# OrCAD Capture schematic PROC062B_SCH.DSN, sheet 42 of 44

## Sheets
42 42. PERIPHERAL POWER SUPPLY: size C; title: PERIPHERAL POWER SUPPLY
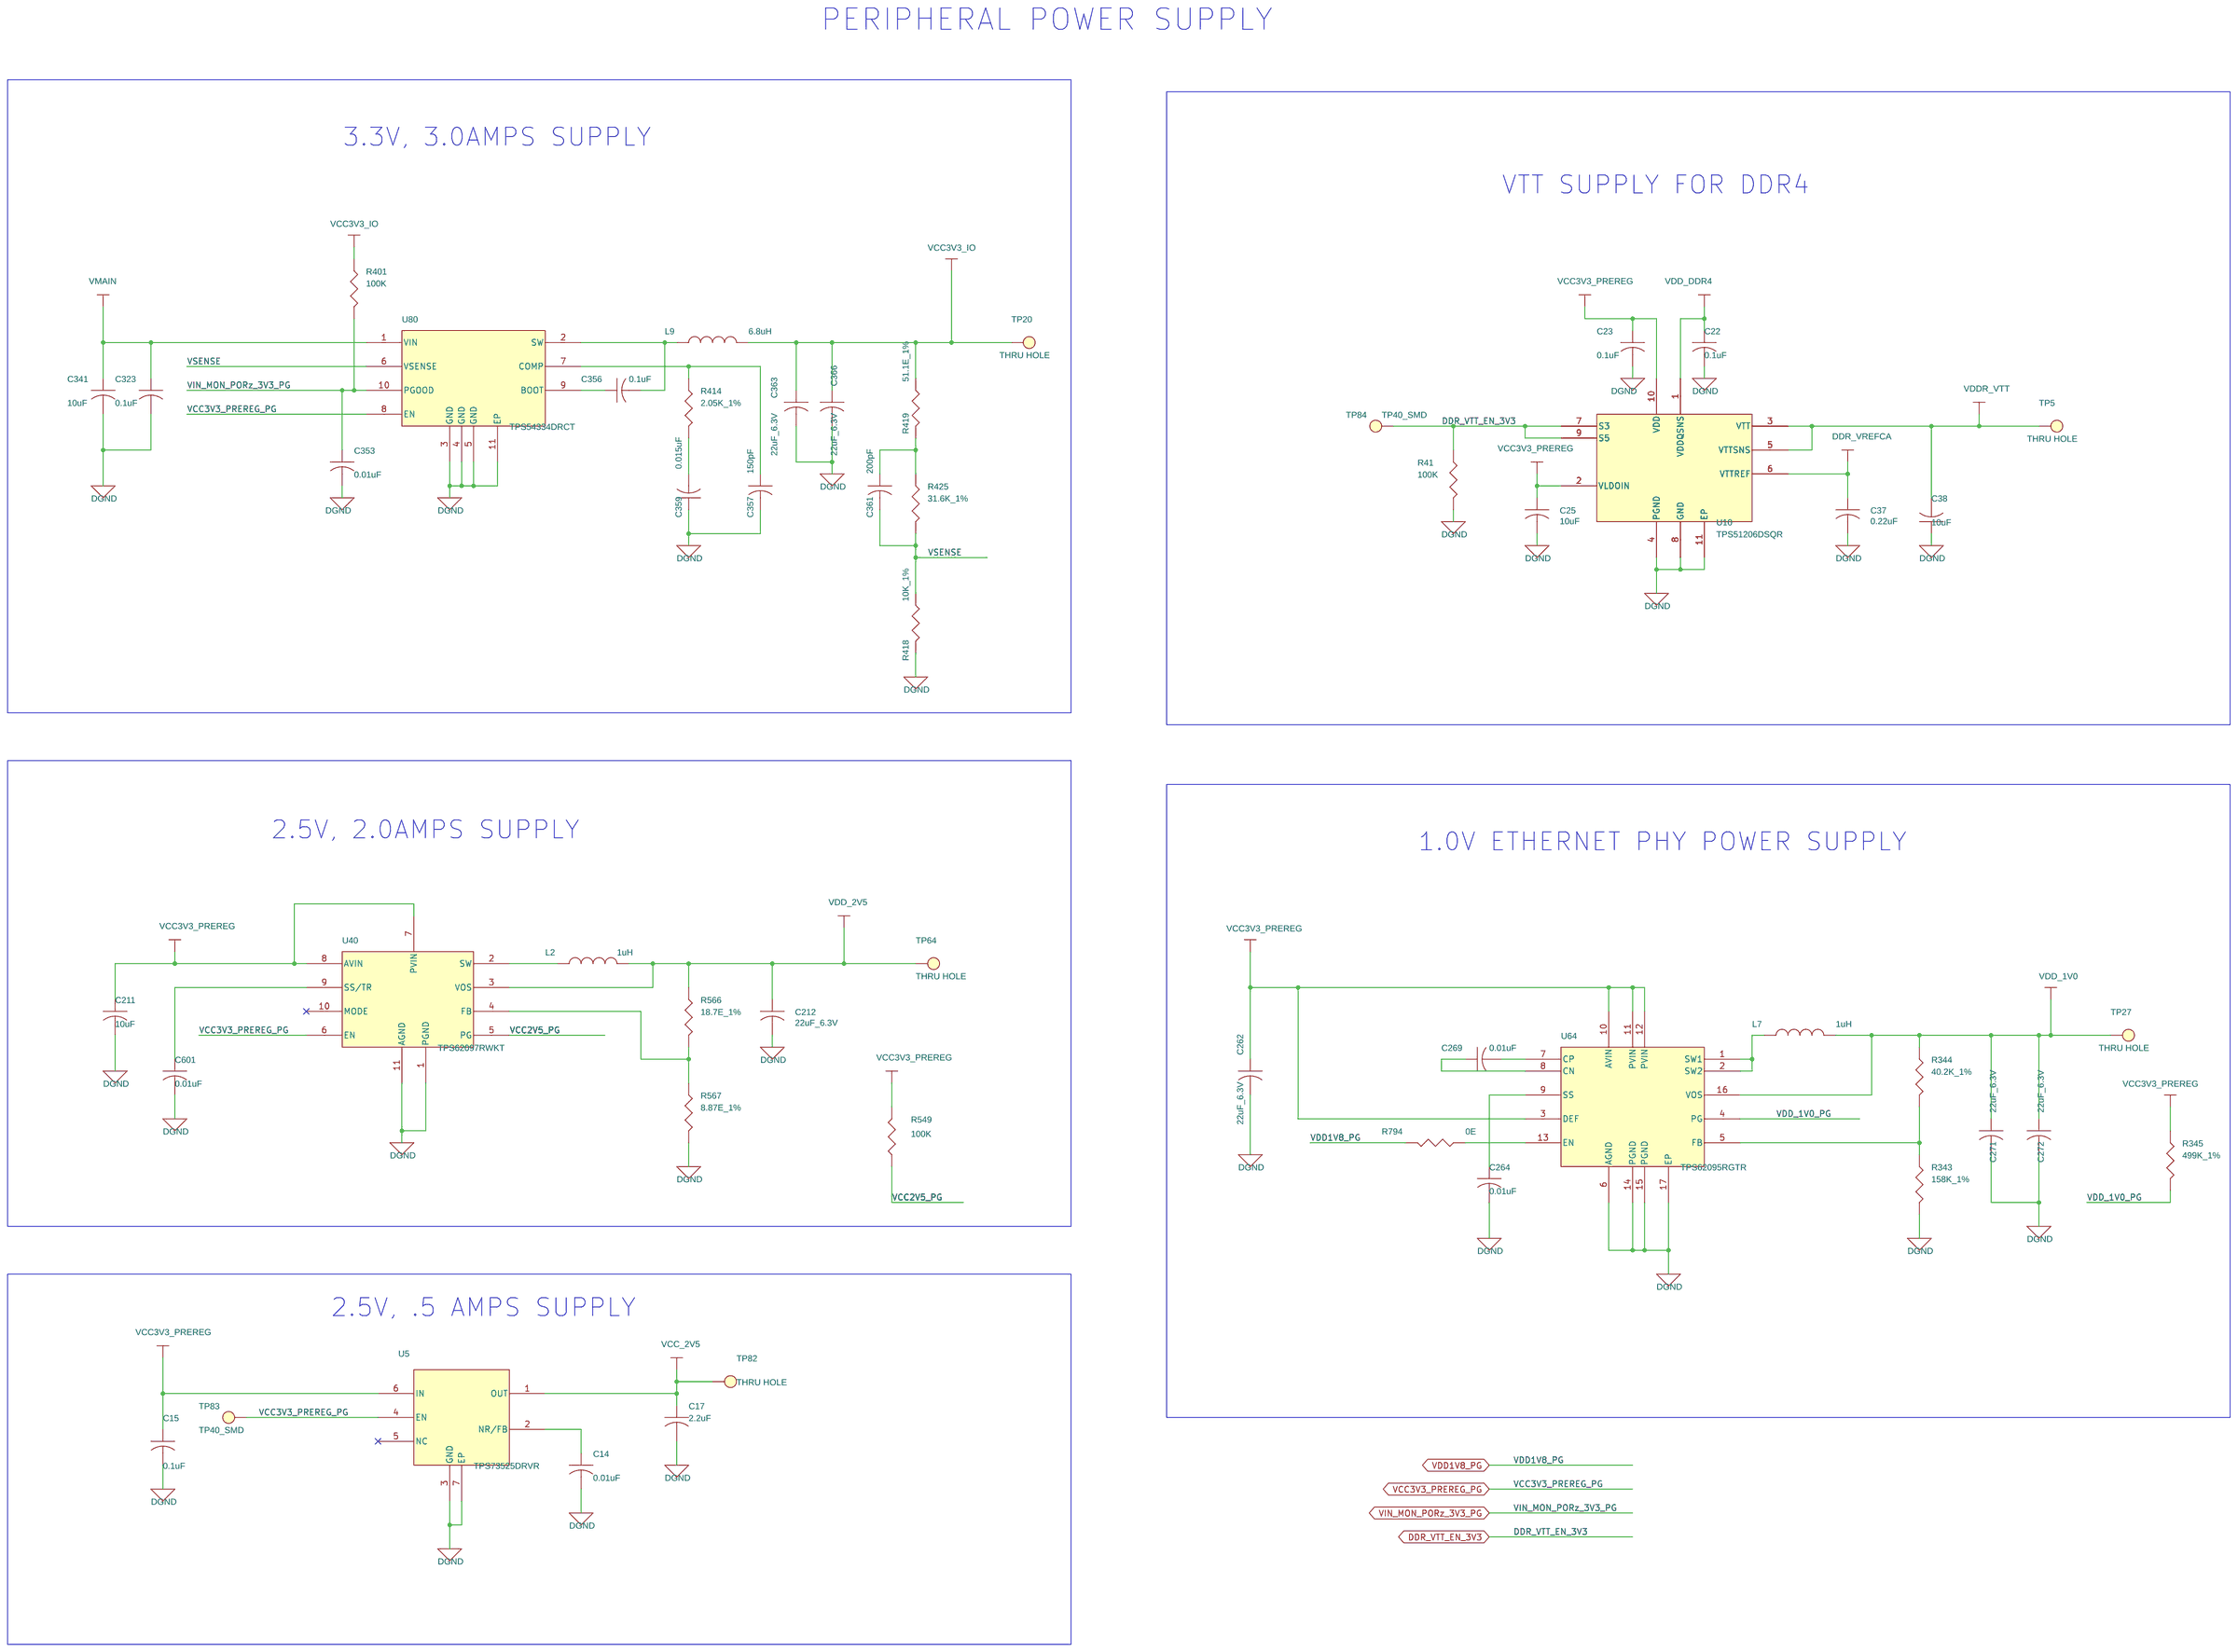
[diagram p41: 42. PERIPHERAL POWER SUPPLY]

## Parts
C14  0.01uF  [CAP0201_0-5]
C15  0.1uF  [CAP0201_0-5]
C17  2.2uF  [CAP0402_0-75]
C22  0.1uF  [CAP0201_0-5]
C23  0.1uF  [CAP0201_0-5]
C25  10uF  [CAP0603_1]
C37  0.22uF  [CAP0402_0-75]
C38  10uF  [CAP0603_1]
C211  10uF  [CAP0603_1]
C212  22uF_6.3V  [CAP0603]
C262  22uF_6.3V  [CAP0603]
C264  0.01uF  [CAP0201_0-5]
C269  0.01uF  [CAP0201_0-5]
C271  22uF_6.3V  [CAP0603]
C272  22uF_6.3V  [CAP0603]
C323  0.1uF  [CAP0603_1]
C341  10uF  [CAP1206_2]
C353  0.01uF  [CAP0201_0-5]
C356  0.1uF  [CAP0201_0-5]
C357  150pF  [CAP0402_0-75]
C359  0.015uF  [CAP0402_0-75]
C361  200pF  [CAP0402_0-75]
C363  22uF_6.3V  [CAP0603]
C366  22uF_6.3V  [CAP0603]
C601  0.01uF  [CAP0201_0-5]
L2  1uH  [IND_IHLP2020AB_210X210_SMD_1-2]
L7  1uH  [IND_XFL4020_170X170_SMD_2-1]
L9  6.8uH  [IND_74439346068_260X270_SMD_6-1]
R41  100K  [RES0402_0-5]
R343  158K_1%  [RES0402_0-5]
R344  40.2K_1%  [RES0402_0-5]
R345  499K_1%  [RES0402]
R401  100K  [RES0402_0-5]
R414  2.05K_1%  [RES0402]
R418  10K_1%  [RES0402_0-5]
R419  51.1E_1%  [RES0402_0-5]
R425  31.6K_1%  [RES0402]
R549  100K  [RES0402_0-5]
R566  18.7E_1%  [RES0402]
R567  8.87E_1%  [RES0402]
R794  0E  [RES0402_0-5]
TP5  THRU HOLE  [TP_40X65]
TP20  THRU HOLE  [TP_40X65]
TP27  THRU HOLE  [TP_40X65]
TP64  THRU HOLE  [TP_40X65]
TP82  THRU HOLE  [TP_40X65]
TP83  TP40_SMD  [TP40_SMD]
TP84  TP40_SMD  [TP40_SMD]
U5  TPS73525DRVR  [SON6_25-59_85X85_0-8]
U10  TPS51206DSQR  [DFN10_15-74_80X80_0-8]
U40  TPS62097RWKT  [VQFNHR11_TPS62097_80X80_1]
U64  TPS62095RGTR  [QFN16_19-68_120X120_1]
U80  TPS54334DRCT  [SON10_19-68_125X125_1]

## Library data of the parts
C14 C264 C269 C353 C601 = CAP: CAP CERAMIC 0.01uF 25V 10% X5R 0201; Chkd/date: MANIRAJA/230118; Crtd /date: MANIRAJA/230118; Custom_Duty: 15%; Customs_HS_Code: 85322990; Distributor_name: DIGIKEY; Distributor_part_number: GRM033R61E103KA12J-ND; Height: 0.33MM; Mfr_name: MURATA; Mfr_part_number: GRM033R61E103KA12J; Mistral Part No: 120018010007-R; Package: 0201; Part_type: CAPACITORS\CERAMIC; Project: TI_MAXIE_CPB; RoHS: RoHS; Temperature: -55°C+85°C; Tolerance: 10%; Voltage: 25V; Wattage: NA; Weight: 0.33mg; Datasheet: Y:\MIS_DATABASE\DATASHEETS\CAPACITORS\GRM033R61E103KA12.PDF
C15 C22 C23 C356 = CAP: CAP CERAMIC 0.1uF 16V 10% X5R 0201; Chkd/date: MANIRAJA/120218; Crtd /date: MANIRAJA/120218; Custom_Duty: 15%; Customs_HS_Code: 85322990; Distributor_name: DIGIKEY; Distributor_part_number: 490-16742-1-ND; Height: 0.33MM; Mfr_name: MURATA; Mfr_part_number: GRM033R61C104KE84J; Mistral Part No: 120009030072-R; Package: 0201; Part_type: CAPACITORS\CERAMIC; Project: TI_MAXIE_CPB; RoHS: RoHS; Temperature: -55°C+85°C; Tolerance: 10%; Voltage: 16V; Wattage: NA; Weight: 0.33mg; Datasheet: Y:\MIS_DATABASE\DATASHEETS\CAPACITORS\GRM033R61C104KE84.PDF
C17 = CAP: CAP CERAMIC 2.2uF 10V 20% X5R 0402; Chkd/date: MANIRAJA/240118; Crtd /date: MANIRAJA/240118; Custom_Duty: 15%; Customs_HS_Code: 85322990; Distributor_name: DIGIKEY; Distributor_part_number: 490-12254-1-ND; Height: 0.55MM; Mfr_name: MURATA; Mfr_part_number: GRT155R61A225ME01D; Mistral Part No: 120018010016-R; Package: 0402; Part_type: CAPACITORS\CERAMIC; Project: TI_MAXIE_CPB; RoHS: RoHS; Temperature: -55°C+85°C; Tolerance: 20%; Voltage: 10V; Wattage: NA; Weight: 0.65mg; Datasheet: Y:\MIS_DATABASE\DATASHEETS\CAPACITORS\GRT155R61A225ME01.PDF
C25 C38 C211 = CAP: CAP CERAMIC 10uF 10V 10% X5R 0603; Chkd/date: MANIRAJA/230118; Crtd /date: MANIRAJA/230118; Custom_Duty: 15%; Customs_HS_Code: 85322990; Distributor_name: DIGIKEY; Distributor_part_number: 478-10766-1-ND; Height: 0.94MM; Mfr_name: AVX CORPORATION; Mfr_part_number: 0603ZD106KAT2A; Mistral Part No: 120010080001-R; Package: 0603; Part_type: CAPACITORS\CERAMIC; Project: TI_MAXIE_CPB; RoHS: RoHS; Temperature: -55°C+85°C; Tolerance: 10%; Voltage: 10V; Wattage: NA; Weight: 2mg; Datasheet: Y:\MIS_DATABASE\DATASHEETS\CAPACITORS\AVX_MLC.PDF
C37 = CAP: CAP CERAMIC 0.22uF 10V 10% X5R 0402; Chkd/date: MANIRAJA/070220; Crtd /date: ALVY/070220; Custom_Duty: 15%; Customs_HS_Code: 85322990; Distributor_name: DIGIKEY; Distributor_part_number: 587-1228-1-ND; Footprint Path: Y:\MIS_DATABASE\Library\ALTIUM_TOOL\PCB_FOOTPRINTS\Altium_Footprint_Lib.PcbLib; Height: 0.55MM; Library Path: Y:\MIS_DATABASE\Library\ALTIUM_TOOL\SCHEMATICS_PARTS\MS_DISCRETE_Library.schlib; Mfr_name: TAIYO YUDEN; Mfr_part_number: LMK105BJ224KV-F; Mistral Part No: 120009030090-R; Package: 0402; Part_type: CAPACITORS\CERAMIC; Project: TI_MAXIE_CPB; RoHS: RoHS; Temperature: -55°C+85°C; Tolerance: 10%; Voltage: 10V; Wattage: NA; Weight: 0.65mg; Datasheet: Y:\MIS_DATABASE\DATASHEETS\CAPACITORS\LMK105BJ224KV-F.PDF
C212 C262 C271 C272 C363 C366 = CAP: CAP CERAMIC 22uF 6.3V 20% X5R 0603; Alternate_mfr_name_A: YAGEO AMERICA; Alternate_mfr_part_number_A: CC0603MRX5R5BB226; Chkd/date: JEBRAN/090915; Crtd /date: JEBRAN/090915; Custom_Duty: 15%; Customs_HS_Code: 85322990; Distributor_name: DIGIKEY; Distributor_name_A: DIGIKEY; Distributor_part_number: 490-7611-2-ND; Distributor_part_number_A: 311-1815-1-ND; Height: 1.00MM; Mfr_name: MURATA; Mfr_part_number: GRM188R60J226MEA0; Mistral Part No: 120015090007-R; Package: 0603; Part_type: CAPACITORS\CERAMIC; Project: OCTBTS_3000; RoHS: RoHS; Temperature: -55°C+85°C; Tolerance: 20%; Voltage: 6.3V; Wattage: NA; Weight: NA; Datasheet: Y:\MIS_DATABASE\DATASHEETS\CAPACITORS\GRM188SERIES.PDF
C323 = CAP: CAP CERAMIC 0.1uF 50V 20% X7R 0603; Chkd/date: MANIRAJA/240118; Crtd /date: MANIRAJA/240118; Custom_Duty: 15%; Customs_HS_Code: 85322990; Distributor_name: DIGIKEY; Distributor_part_number: 399-7845-1-ND; Height: 0.95MM; Mfr_name: KEMET; Mfr_part_number: C0603C104M5RACTU; Mistral Part No: 120018010021-R; Package: 0603; Part_type: CAPACITORS\CERAMIC; Project: TI_MAXIE_CPB; RoHS: RoHS; Temperature: -55°C+125°C; Tolerance: 20%; Voltage: 50V; Wattage: NA; Weight: 2mg; Datasheet: Y:\MIS_DATABASE\DATASHEETS\CAPACITORS\KEMET-X7R-SER.PDF
C341 = CAP: CAP CERAMIC 10uF 50V 10% X5R 1206; Chkd/date: VASANTHA/190814; Crtd /date: BAVISH/230611; Custom_Duty: 15%; Customs_HS_Code: 85322990; Distributor_name: DIGIKEY; Distributor_part_number: 445-5998-1-ND; Footprint Path: Y:\MIS_DATABASE\Library\ALTIUM_TOOL\PCB_FOOTPRINTS\Altium_Footprint_Lib.PcbLib; Height: 1.90MM; Library Path: Y:\MIS_DATABASE\Library\ALTIUM_TOOL\SCHEMATICS_PARTS\MS_DISCRETE_Library.schlib; Mfr_name: TDK CORPORATION; Mfr_part_number: C3216X5R1H106K160AB; Mistral Part No: 120016030005-R; Package: 1206; Part_type: CAPACITORS\CERAMIC; Project: ITS-SINGAL_COND_CARD; RoHS: RoHS; Temperature: -55°C+85°C; Tolerance: 10%; Voltage: 50V; Wattage: NA; Weight: 16.2mg; Datasheet: Y:\MIS_DATABASE\DATASHEETS\CAPACITORS\TDK_C-SER-JUL17.PDF
C357 = CAP: CAP CERAMIC 150pF 50V 10% X7R 0402; Chkd/date: MANIRAJA/240118; Crtd /date: MANIRAJA/240118; Custom_Duty: 15%; Customs_HS_Code: 85322990; Distributor_name: DIGIKEY; Distributor_part_number: 732-7551-1-ND; Height: 0.55MM; Mfr_name: WURTH ELECTRONICS; Mfr_part_number: 885012205056; Mistral Part No: 120018010022-R; Package: 0402; Part_type: CAPACITORS\CERAMIC; Project: TI_MAXIE_CPB; RoHS: RoHS; Temperature: -55°C+125°C; Tolerance: 10%; Voltage: 50V; Wattage: NA; Weight: 0.65mg; Datasheet: Y:\MIS_DATABASE\DATASHEETS\CAPACITORS\'885012205056.PDF
C359 = CAP: CAP CERAMIC 0.015uF 50V 10% X7R 0402; Chkd/date: ALVY/100919; Crtd /date: ALVY/100919; Custom_Duty: 15%; Customs_HS_Code: 85322990; Distributor_name: DIGIKEY; Distributor_part_number: 399-11115-1-ND; Footprint Path: Y:\MIS_DATABASE\Library\ALTIUM_TOOL\PCB_FOOTPRINTS\Altium_Footprint_Lib.PcbLib; Height: 0.55MM; Library Path: Y:\MIS_DATABASE\Library\ALTIUM_TOOL\SCHEMATICS_PARTS\MS_DISCRETE_Library.schlib; Mfr_name: KEMET; Mfr_part_number: C0402C153K5RACTU; Mistral Part No: 120010030008-R; Package: 0402; Part_type: CAPACITORS\CERAMIC; Project: AM654x_SOM; RoHS: RoHS; Temperature: -55°C+125°C; Tolerance: 10%; Voltage: 50V; Wattage: NA; Weight: 0.65mg; Datasheet: Y:\MIS_DATABASE\DATASHEETS\CAPACITORS\KEMET-C-X7R.PDF
C361 = CAP: CAP CERAMIC 200pF 50V 5% C0G(NP0) AUTO 0402; Chkd/date: MANIRAJA/070220; Crtd /date: ALVY/070220; Custom_Duty: 15%; Customs_HS_Code: 85322990; Distributor_name: DIGIKEY; Distributor_part_number: GCM1555C1H201JA16D-ND; Footprint Path: Y:\MIS_DATABASE\Library\ALTIUM_TOOL\PCB_FOOTPRINTS\Altium_Footprint_Lib.PcbLib; Height: 0.55MM; Library Path: Y:\MIS_DATABASE\Library\ALTIUM_TOOL\SCHEMATICS_PARTS\MS_DISCRETE_Library.schlib; Mfr_name: MURATA; Mfr_part_number: GCM1555C1H201JA16D; Mistral Part No: 120020020002-R; Package: 0402; Part_type: CAPACITORS\CERAMIC; Project: TI_MAXIE_CPB; RoHS: RoHS; Temperature: -55°C+125°C; Tolerance: 5%; Voltage: 50V; Wattage: NA; Weight: 6mg; Datasheet: Y:\MIS_DATABASE\DATASHEETS\CAPACITORS\GCM1555C1H201JA16D.PDF
L2 = INDUCTOR: IND POWER 1uH 4.4A 20% SMD; Chkd/date: VASANTHA/170317; Crtd /date: MANIRAJA/160317; Custom_Duty: 24%; Customs_HS_Code: 85437099; Distributor_name: DIGIKEY; Distributor_part_number: 541-1704-1-ND; Height: 1.20MM; Mfr_name: VISHAY; Mfr_part_number: IHLP2020ABER1R0M01; Mistral Part No: 130017030015-R; Package: SMD; Project: ADA_3U_FMC; RoHS: RoHS; Temperature: -55°C+125°C; Tolerance: 20%; Voltage: NA; Wattage: NA; Weight: 200mg; Datasheet: Y:\MIS_DATABASE\DATASHEETS\DISCRETES\INDUCTORS\IHLP2020AB.PDF
L7 = INDUCTOR: IND POWER 1uH 8A 20% SMD; Chkd/date: VASANTHA/050117; Crtd /date: CHAITHANYA/290312; Custom_Duty: 24%; Customs_HS_Code: 85437099; Distributor_name: MOUSER; Distributor_part_number: 994-XFL4020-102MEC; Footprint Path: Y:\MIS_DATABASE\Library\ALTIUM_TOOL\PCB_FOOTPRINTS\Altium_Footprint_Lib.PcbLib; Height: 2.10MM; Library Path: Y:\MIS_DATABASE\Library\ALTIUM_TOOL\SCHEMATICS_PARTS\MS_DISCRETE_Library.schlib; Mfr_name: COILCRAFT; Mfr_part_number: XFL4020-102MEC; Mistral Part No: 130012030053-R; Package: SMD; Project: IRIS; RoHS: RoHS; Temperature: -40°C+125°C; Tolerance: 20%; Voltage: NA; Wattage: NA; Weight: 169mg; Datasheet: Y:\MIS_DATABASE\DATASHEETS\DISCRETES\INDUCTORS\XFL4020.PDF
L9 = INDUCTOR: IND POWER 6.8uH 6.5A 20% SMD; Chkd/date: MANIRAJA/171017; Crtd /date: MANIRAJA/171017; Custom_Duty: 24%; Customs_HS_Code: 85437099; Distributor_name: DIGIKEY; Distributor_part_number: 732-10705-1-ND; Height: 6.10MM; Mfr_name: WURTH ELECTRONICS; Mfr_part_number: 74439346068; Mistral Part No: 130017100019-R; Package: SMD; Project: TI_MAXIE_CPB; RoHS: RoHS; Temperature: -40°C+125°C; Tolerance: 20%; Voltage: NA; Wattage: NA; Weight: NA; Datasheet: Y:\MIS_DATABASE\DATASHEETS\DISCRETES\INDUCTORS\74439346068.PDF
R41 R401 R549 = RESISTOR: RES 100K 1/16W 5% 0402; Chkd/date: VASANTHA/061216; Crtd /date: BAVISH/010611; Custom_Duty: 15%; Customs_HS_Code: 85332119; Distributor_name: DIGIKEY; Distributor_part_number: 541-100KJCT-ND; Height: 0.40MM; Mfr_name: VISHAY; Mfr_part_number: CRCW0402100KJNED; Mistral Part No: 110011060002-R; Package: 0402; Part_type: RESISTORS\FIXED; Project: AM4515_EVM_LCD; RoHS: RoHS; Temperature: -55°C+155°C; Tolerance: 5%; Voltage: NA; Wattage: 1/16W; Weight: 0.65mg; Datasheet: Y:\MIS_DATABASE\DATASHEETS\RESISTORS\CRCW0603.PDF
R343 = RESISTOR: RES 158K 1/16W 1% 0402; Chkd/date: MANIRAJA/031017; Crtd /date: MANIRAJA/031017; Custom_Duty: 15%; Customs_HS_Code: 85332119; Distributor_name: DIGIKEY; Distributor_part_number: YAG2990CT-ND; Height: 0.40MM; Mfr_name: YAGEO AMERICA; Mfr_part_number: RC0402FR-07158KL; Mistral Part No: 110017100001-R; Package: 0402; Part_type: RESISTORS\FIXED; Project: TI_MAXIE_CPB; RoHS: RoHS; Temperature: -55°C+155°C; Tolerance: 1%; Voltage: NA; Wattage: 1/16W; Weight: 0.65mg; Datasheet: Y:\MIS_DATABASE\DATASHEETS\RESISTORS\YAGEO-RC0402.PDF
R344 = RESISTOR: RES 40.2K 1/16W 1% 0402; Chkd/date: VASANTHA/291216; Crtd /date: MAZHAR/170505; Custom_Duty: 15%; Customs_HS_Code: 85332119; Distributor_name: DIGIKEY; Distributor_part_number: 311-40.2KLRDKR-ND; Footprint Path: Y:\MIS_DATABASE\Library\ALTIUM_TOOL\PCB_FOOTPRINTS\Altium_Footprint_Lib.PcbLib; Height: 0.40MM; Library Path: Y:\MIS_DATABASE\Library\ALTIUM_TOOL\SCHEMATICS_PARTS\MS_DISCRETE_Library.schlib; Mfr_name: YAGEO AMERICA; Mfr_part_number: RC0402FR-0740K2L; Mistral Part No: 110009030811; Package: 0402; Part_type: RESISTORS\FIXED; Project: G4SLIM; RoHS: RoHS; Temperature: -55°C+155°C; Tolerance: 1%; Voltage: NA; Wattage: 1/16W; Weight: 0.65mg; Datasheet: Y:\MIS_DATABASE\DATASHEETS\RESISTORS\YAGEO_RES.PDF
R345 = RESISTOR: RES 499K 1/16W 1% 0402; Chkd/date: SUHAS/290910; Crtd /date: MAZHAR/240909; Custom_Duty: 15%; Customs_HS_Code: 85332119; Distributor_name: DIGIKEY; Distributor_part_number: 311-499KLRCT-ND; Height: 0.40MM; Mfr_name: YAGEO AMERICA; Mfr_part_number: RC0402FR-07499KL; Mistral Part No: 110009090015-P; Package: 0402; Part_type: RESISTORS\FIXED; Project: GOLDEN-I; RoHS: Pb-Free; Temperature: -55°C+155°C; Tolerance: 1%; Voltage: 50V; Wattage: 1/16W; Weight: 0.8g/1000pcs; Datasheet: Y:\MIS_DATABASE\DATASHEETS\RESISTORS\YAGEO-RC0402.PDF
R414 = RESISTOR: RES 2.05K 1/10W 1% 0402; Chkd/date: NAVEED/261214; Crtd /date: JEBRAN/271114; Custom_Duty: 15%; Customs_HS_Code: 85332119; Distributor_name: DIGIKEY; Distributor_part_number: P2.05KLCT-ND; Height: 0.40MM; Mfr_name: PANASONIC; Mfr_part_number: ERJ-2RKF2051X; Mistral Part No: 110014110019-R; Package: 0402; Part_type: RESISTORS\FIXED; Project: ZK BIOMETRIC; RoHS: RoHS; Temperature: -55°C+125°C; Tolerance: 1%; Voltage: NA; Wattage: 1/10W; Weight: NA; Datasheet: Y:\MIS_DATABASE\DATASHEETS\RESISTORS\ERJ-2R.PDF
R418 = RESISTOR: RES 10K 1/16W 1% 0402; Chkd/date: VASANTHA/201216; Crtd /date: GEETHA/290506; Custom_Duty: 15%; Customs_HS_Code: 85332119; Distributor_name: DIGIKEY; Distributor_part_number: 311-10.0KLRTR-ND; Footprint Path: Y:\MIS_DATABASE\Library\ALTIUM_TOOL\PCB_FOOTPRINTS\Altium_Footprint_Lib.PcbLib; Height: 0.40MM; Library Path: Y:\MIS_DATABASE\Library\ALTIUM_TOOL\SCHEMATICS_PARTS\MS_DISCRETE_Library.schlib; Mfr_name: YAGEO AMERICA; Mfr_part_number: RC0402FR-0710KL; Mistral Part No: 110009030220-P; Package: 0402; Part_type: RESISTORS\FIXED; Project: VOCERA; RoHS: Pb-Free; Temperature: -55°C+155°C; Tolerance: 1%; Voltage: NA; Wattage: 1/16W; Weight: 0.65mg; Datasheet: Y:\MIS_DATABASE\DATASHEETS\RESISTORS\YAGEO-RC0402.PDF
R419 = RESISTOR: RES 51.1E 1/16W 1% 0402; Chkd/date: MANIRAJA/280617; Crtd /date: MANIRAJA/280617; Custom_Duty: 15%; Customs_HS_Code: 85332119; Distributor_name: DIGIKEY; Distributor_part_number: 311-51.1LRCT-ND; Height: 0.40MM; Mfr_name: YAGEO AMERICA; Mfr_part_number: RC0402FR-0751R1L; Mistral Part No: 110017060001-R; Package: 0402; Part_type: RESISTORS\FIXED; Project: TI_SVB_CONTROLLER CARD; RoHS: RoHS; Temperature: -55°C+155°C; Tolerance: 1%; Voltage: NA; Wattage: 1/16W; Weight: 0.65mg; Datasheet: Y:\MIS_DATABASE\DATASHEETS\RESISTORS\YAGEO-RC0402.PDF
R425 = RESISTOR: RES 31.6K 1/10W 1% 0402; Chkd/date: SHREESHAIL/070606; Crtd /date: SHREESHAIL/070606; Custom_Duty: 15%; Customs_HS_Code: 85332119; Distributor_name: DIGIKEY; Distributor_part_number: P31.6KLCT-ND; Footprint Path: Y:\MIS_DATABASE\Library\ALTIUM_TOOL\PCB_FOOTPRINTS\Altium_Footprint_Lib.PcbLib; Height: 0.40MM; Library Path: Y:\MIS_DATABASE\Library\ALTIUM_TOOL\SCHEMATICS_PARTS\MS_DISCRETE_Library.schlib; Mfr_name: PANASONIC-ECG; Mfr_part_number: ERJ-2RKF3162X; Mistral Part No: 110009030679-R; Package: 0402; Part_type: RESISTORS\FIXED; Project: VOCERA; RoHS: RoHS; Tolerance: 1%; Wattage: 1/10W; Datasheet: Y:\MIS_DATABASE\DATASHEETS\RESISTORS\PAN_ERJ.PDF
R566 = RESISTOR: RES 18.7E 1/16W 1% 0402; Chkd/date: SUHAS/230910; Crtd /date: MUDDU/080910; Custom_Duty: 15%; Customs_HS_Code: 85332119; Distributor_name: DIGIKEY; Distributor_part_number: 541-18.7LCT-ND; Height: 0.40MM; Mfr_name: VISHAY; Mfr_part_number: CRCW040218R7FKED; Mistral Part No: 110010090023-P; Package: 0402; Part_type: RESISTORS\FIXED; Project: ITS; RoHS: Pb-Free; Temperature: -55°C+125°C; Tolerance: 1%; Voltage: 50V; Wattage: 1/16W; Weight: 0.65g/1000pcs; Datasheet: Y:\MIS_DATABASE\DATASHEETS\RESISTORS\CRCW0603.PDF
R567 = RESISTOR: RES 8.87E 1/16W 1% 0402; Chkd/date: USMAN/100114; Crtd /date: JAGADISH/090114; Custom_Duty: 15%; Customs_HS_Code: 85332119; Distributor_name: DIGIKEY; Distributor_part_number: 541-8.87LLCT-ND; Height: 0.40MM; Mfr_name: VISHAY; Mfr_part_number: CRCW04028R87FKED; Mistral Part No: 110014010002-R; Package: 0402; Part_type: RESISTORS\FIXED; Project: ITS2_CC; RoHS: RoHS; Temperature: -55°C+155°C; Tolerance: 1%; Voltage: NA; Wattage: 1/16W; Weight: 0.65mg; Datasheet: Y:\MIS_DATABASE\DATASHEETS\RESISTORS\CRCW0603.PDF
R794 = RESISTOR: RES 0E 1/16W 0402; Chkd/date: VASANTHA/201216; Crtd /date: MUDDU/190810; Custom_Duty: 15%; Customs_HS_Code: 85332119; Distributor_name: DIGIKEY; Distributor_part_number: 541-0.0JCT-ND; Footprint Path: Y:\MIS_DATABASE\Library\ALTIUM_TOOL\PCB_FOOTPRINTS\Altium_Footprint_Lib.PcbLib; Height: 0.40MM; Library Path: Y:\MIS_DATABASE\Library\ALTIUM_TOOL\SCHEMATICS_PARTS\MS_DISCRETE_Library.schlib; Mfr_name: VISHAY; Mfr_part_number: CRCW04020000Z0ED; Mistral Part No: 110010080019-P; Package: 0402; Part_type: RESISTORS\FIXED; Project: PB_BUGBASE; RoHS: Pb-Free; Temperature: -55°C+155°C; Tolerance: NA; Voltage: NA; Wattage: 1/16W; Weight: 0.65g/1000pcs; Datasheet: Y:\MIS_DATABASE\DATASHEETS\RESISTORS\CRCW0603.PDF
TP5 TP20 TP27 TP64 TP82 = TESTPOINT: TESTPOINT 1.0MM DRILL PTH; Chkd/date: MAZHAR/271211; Crtd /date: SHREESHAIL/041005; Distributor_name: NA; Distributor_part_number: NA; Height: NA; Mfr_name: LOCAL; Mistral Part No: 130009030938; Package: THRU-HOLE; Part_type: MISC\TESTPOINT; Project: HSE; Datasheet: NA
TP83 TP84 = TESTPOINT: TESTPOINT CIR 40 SMD; Chkd/date: MAZHAR/190505; Crtd /date: MAZHAR/190505; Distributor_name: NA; Distributor_part_number: NA; Footprint Path: Y:\MIS_DATABASE\Library\ALTIUM_TOOL\PCB_FOOTPRINTS\Altium_Footprint_Lib.PcbLib; Height: NA; Library Path: Y:\MIS_DATABASE\Library\ALTIUM_TOOL\SCHEMATICS_PARTS\MS_DISCRETE_Library.schlib; MECHANICAL 3D STEP FILE: NA; Mfr_name: LOCAL; Mistral Part No: 130009030933; Package: SMD; Project: RAINIER-3; RoHS: NA; Temperature: NA; Tolerance: NA; Voltage: NA; Wattage: NA; Weight: NA; Datasheet: NA
U5 = TPS73501DRVR_SON6: IC 500mA LOW DROPOUT HIGH PSRR LINEAR REGULATOR SON6; Chkd/date: MANIRAJA/161117; Crtd /date: MANIRAJA/161117; Custom_Duty: 15%; Customs_HS_Code: 85423100; Distributor_name: DIGIKEY; Distributor_part_number: 296-27480-1-ND; Height: 0.80MM; Mfr_name: TEXAS INSTRUMENTS; Mistral Part No: 142017110007-R; Package: SON6; Part_type: ICS\POWER\VOLTAGE REGULATOR; Project: TI_MAXIE_CPB; RoHS: RoHS; Temperature: -40°C+125°C; Tolerance: NA; Voltage: NA; Wattage: NA; Weight: 9.7mg; Datasheet: Y:\MIS_DATABASE\DATASHEETS\ICS\POWER\TPS735.PDF
U10 = TPS51206DSQR_WSON10: IC SINK/SOURCE DDR TERMINATION REGULATOR WSON10; Chkd/date: MANIRAJA/220917; Crtd /date: MANIRAJA/220917; Custom_Duty: 15%; Customs_HS_Code: 85423100; Distributor_name: DIGIKEY; Distributor_part_number: 296-28767-1-ND; Height: 0.80MM; Mfr_name: TEXAS INSTRUMENTS; Mistral Part No: 142017090016-R; Package: WSON10; Part_type: ICS\POWER\VOLTAGE REGULATOR; Project: TI_MAXIE_CPB; RoHS: RoHS; Temperature: -40°C+85°C; Tolerance: NA; Voltage: NA; Wattage: NA; Weight: NA; Datasheet: Y:\MIS_DATABASE\DATASHEETS\ICS\POWER\TPS51206.PDF
U40 = TPS62097RWKT_VQFNHR11: IC 2A SYNCHRONOUS STEP DOWN CONVERTER WITH IDCS CONTROL VQFN-HR11; Chkd/date: MANIRAJA/270917; Crtd /date: MANIRAJA/270917; Custom_Duty: 15%; Customs_HS_Code: 85423100; Distributor_name: DIGIKEY; Distributor_part_number: 296-43330-1-ND; Height: 1.00MM; Mfr_name: TEXAS INSTRUMENTS; Mistral Part No: 142017090025-R; Package: VQFN-HR11; Part_type: ICS\POWER\CONVERTER; Project: TI_MAXIE_CPB; RoHS: RoHS; Temperature: -40°C+125°C; Tolerance: NA; Voltage: NA; Wattage: NA; Weight: NA; Datasheet: Y:\MIS_DATABASE\DATASHEETS\ICS\POWER\TPS62097.PDF
U64 = TPS62095RGTR_VQFN16: IC 4A STEP DOWN CONVERTER WITH DCS CONTROL VQFN16; Chkd/date: MANIRAJA/031017; Crtd /date: MANIRAJA/031017; Custom_Duty: 15%; Customs_HS_Code: 85423100; Distributor_name: DIGIKEY; Distributor_part_number: 296-40833-1-ND; Height: 1.00MM; Mfr_name: TEXAS INSTRUMENTS; Mistral Part No: 142017100001-R; Package: VQFN16; Part_type: ICS\POWER\CONVERTER; Project: TI_MAXIE_CPB; RoHS: RoHS; Temperature: -40°C+85°C; Tolerance: NA; Voltage: NA; Wattage: NA; Weight: NA; Datasheet: Y:\MIS_DATABASE\DATASHEETS\ICS\POWER\TPS62095.PDF
U80 = TPS54334DRCT_VSON10: IC 3A O/P CURRENT SYNCHRONOUS STEP DOWN VOLTAGE CONVERTER VSON10; Chkd/date: MANIRAJA/270917; Crtd /date: MANIRAJA/270917; Custom_Duty: 15%; Customs_HS_Code: 85423100; Distributor_name: DIGIKEY; Distributor_part_number: 296-42172-2-ND; Height: 1.00MM; Mfr_name: TEXAS INSTRUMENTS; Mistral Part No: 142017090024-R; Package: VSON10; Part_type: ICS\POWER\CONVERTER; Project: TI_MAXIE_CPB; RoHS: RoHS; Temperature: -40°C+85°C; Tolerance: NA; Voltage: NA; Wattage: NA; Weight: 30mg; Datasheet: Y:\MIS_DATABASE\DATASHEETS\ICS\POWER\TPS54334.PDF

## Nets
DGND: C14.2 C15.2 C17.2 C22.2 C23.2 C25.2 C37.2 C38.1 C211.2 C212.2 C262.2 C264.2 C271.2 C272.2 C323.2 C341.2 C353.2 C357.2 C359.1 C363.2 C366.2 C601.2 R41.2 R343.2 R418.2 R567.2 U5.3(GND) U5.7(EP) U10.4(PGND) U10.8(GND) U10.11(EP) U40.1(PGND) U40.11(AGND) U64.6(AGND) U64.14(PGND) U64.15(PGND) U64.17(EP) U80.3(GND) U80.4(GND) U80.5(GND) U80.11(EP) ; also on sheet 11 12 13 14 15 16 17 18 19 20 21 22 23 24 25 26 27 28 29 30 31 32 33 34 35 36 37 38 39 40 41 43 44
VCC2V5_PG: R549.1 U40.5(PG)
VCC3V3_IO: C363.1 C366.1 L9.2 R401.1 R419.1 TP20.1(TP) ; also on sheet 11 18 19 20 21 22 23 24 25 26 28 29 30 31 33 34 35 36 37 38 39 41 43 44
VCC3V3_PREREG: C15.1 C23.1 C25.1 C211.1 C262.1 R345.1 R549.2 U5.6(IN) U10.2(VLDOIN) U10.10(VDD) U40.7(PVIN) U40.8(AVIN) U64.3(DEF) U64.10(AVIN) U64.11(PVIN) U64.12(PVIN) ; also on sheet 13 39 40 41
VCC3V3_PREREG_PG: TP83.1(TP) U5.4(EN) U40.6(EN) U80.8(EN) ; also on sheet 40
VCC_2V5: C17.1 TP82.1(TP) U5.1(OUT) ; also on sheet 17 35
VDD1V8_PG: R794.2 ; also on sheet 41
VDD_1V0: C271.1 C272.1 L7.2 R344.1 TP27.1(TP) U64.16(VOS) ; also on sheet 13 21 22 23 33 35
VDD_1V0_PG: R345.2 U64.4(PG)
VDD_2V5: C212.1 L2.2 R566.1 TP64.1(TP) U40.3(VOS) ; also on sheet 21 22 23 33
VDD_DDR4: C22.1 U10.1(VDDQSNS) ; also on sheet 16 17 26
VDDR_VTT: C38.2 TP5.1(TP) U10.3(VTT) U10.5(VTTSNS) ; also on sheet 17
VIN_MON_PORz_3V3_PG: C353.1 R401.2 U80.10(PGOOD) ; also on sheet 39 41
DDR_VREFCA: C37.1 U10.6(VTTREF) ; also on sheet 16 17
DDR_VTT_EN_3V3: R41.1 TP84.1(TP) U10.7(S3) U10.9(S5) ; also on sheet 37
VMAIN: C323.1 C341.1 U80.1(VIN) ; also on sheet 39 40 43
VSENSE: C361.2 R418.1 R425.2 U80.6(VSENSE)
N17785459: C357.1 R414.1 U80.7(COMP)
N17785463: C359.2 R414.2
N17785477: C356.2 L9.1 U80.2(SW)
N17785481: C356.1 U80.9(BOOT)
N17785497: C361.1 R419.2 R425.1
N17785579: L7.1 U64.1(SW1) U64.2(SW2)
N17785692: C269.2 U64.7(CP)
N17785694: C269.1 U64.8(CN)
N17785722: R343.1 R344.2 U64.5(FB)
N17786037: L2.1 U40.2(SW)
N17786049: R566.2 R567.1 U40.4(FB)
N19031494: C601.1 U40.9(SS/TR)
N19031660: C264.1 U64.9(SS)
N20142928: C14.1 U5.2(NR/FB)
N24136473: R794.1 U64.13(EN)

Not connected (* = marked no-connect by the designer): U5 5(NC)*; U40 10(MODE)*

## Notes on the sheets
sheet 42
- PERIPHERAL POWER SUPPLY
- 3.3V, 3.0AMPS SUPPLY
- VTT SUPPLY FOR DDR4
- 2.5V, 2.0AMPS SUPPLY
- 1.0V ETHERNET PHY POWER SUPPLY
- 2.5V, .5 AMPS SUPPLY
